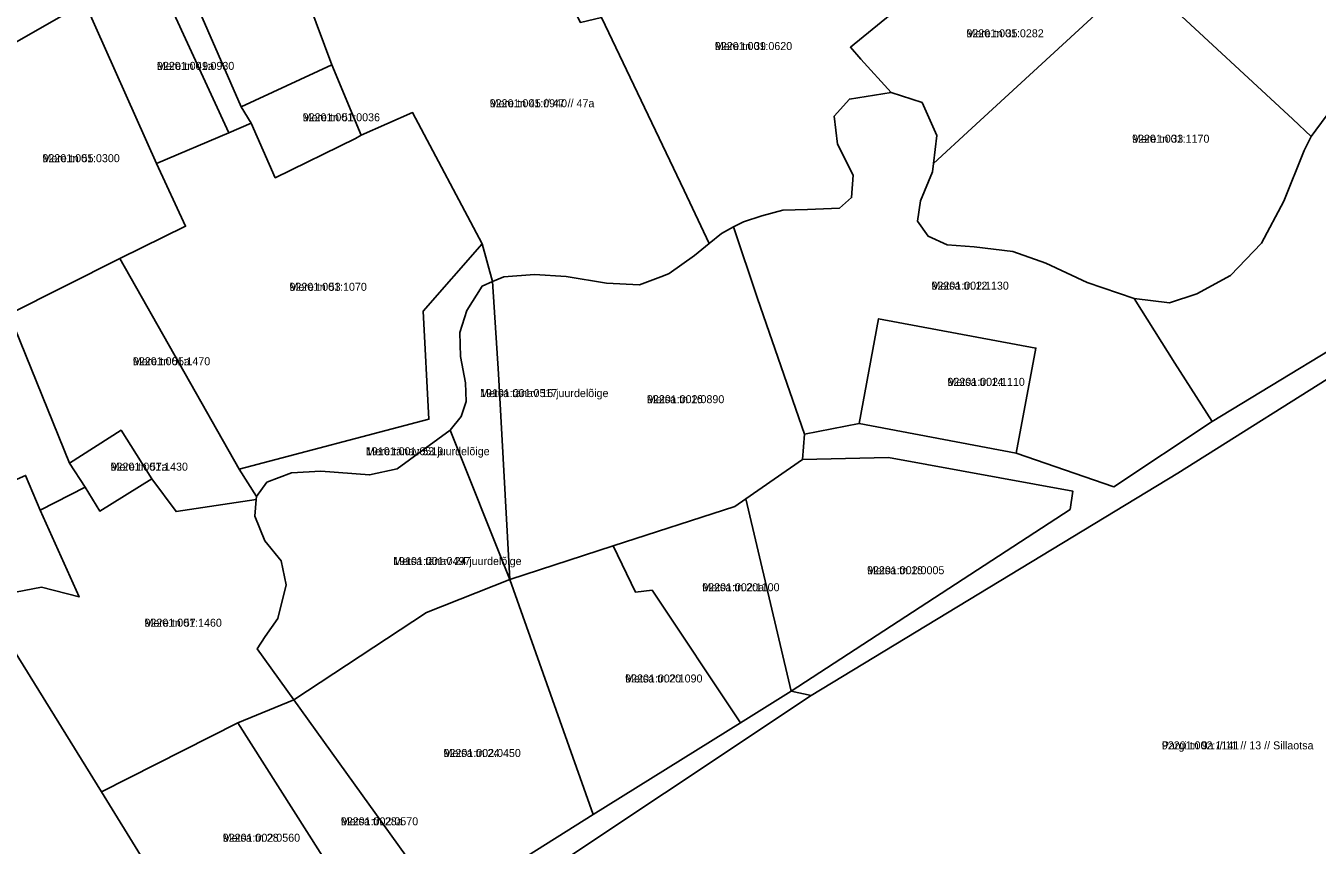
# Model space of a CAD drawing. Extents: x 601493 to 643081, y 6584980 to 6634019.
# Drawn here: x 610866.3 to 611108.4, y 6605821.9 to 6605975.5 of the extents above; entities that cross this region are included whole.
import ezdxf

# ---------------------------------------------------------------- set-up
doc = ezdxf.new("R2010")
doc.units = 0
for name, color, linetype in [('L_AADRESS', 7, 'Continuous'), ('PIIR', 7, 'Continuous'), ('TUNNUS', 7, 'Continuous')]:
    doc.layers.add(name, color=color, linetype=linetype)

msp = doc.modelspace()

# ---------------------------------------------------------------- linework, layer by layer
at = {"layer": 'PIIR'}
for points in [[(611128.64, 6606165.01), (611097.49, 6606138.32), (611089.51, 6606133.5), (611038.62, 6606094.13), (611015.12, 6606075.83), (610999.16, 6606063.8), (610995.18, 6606060.82), (610969.72, 6606041.76), (610962.39, 6606036.06), (610945.03, 6606023.2), (610934.02, 6606015.29), (610912.09, 6605999.25), (610894.18, 6605989.02), (610906.68, 6605960.32), (610908.5, 6605957.28), (610904.36, 6605955.48), (610889.96, 6605986.73), (610877.35, 6605979.85), (610842.57, 6605960.03)], [(611028.31, 6605977.57), (611020.89, 6605971.5), (611022.85, 6605969.3), (611028.54, 6605963.01), (611020.7, 6605961.78), (611017.81, 6605958.58), (611018.43, 6605953.33), (611021.42, 6605947.55), (611021.1, 6605943.32), (611018.83, 6605941.37), (611012.85, 6605941.11), (611008.22, 6605940.98), (611004.3, 6605939.92), (611000.81, 6605938.8), (610998.97, 6605937.83), (610996.69, 6605936.59), (610994.4, 6605934.72), (610989.72, 6605944.68), (610974.24, 6605977.06)], [(610863.17, 6605921.48), (610874.48, 6605893.56), (610877.42, 6605889.07), (610868.99, 6605884.72), (610866.22, 6605891.26)], [(610944.64, 6605810.06), (610972.65, 6605827.71), (611000.25, 6605844.9), (611009.76, 6605850.83), (611013.55, 6605849.98), (610931.04, 6605795.1)]]:
    msp.add_lwpolyline(points, dxfattribs=at)
for points in [[(611039.61, 6606017.31), (611054.32, 6606028.38), (611056.76, 6606025.9), (611072.83, 6606007.94), (611094.39, 6605989.62), (611096.54, 6605991.79), (611117.79, 6605970.79), (611120.89, 6605967.72), (611118.94, 6605965.75), (611110.9, 6605959.65), (611110.08, 6605958.56), (611107.28, 6605954.8), (611103.8, 6605958.04), (611079.61, 6605980.43), (611073.09, 6605983.62)], [(610912.09, 6605999.25), (610934.02, 6606015.29), (610947.98, 6605988.25), (610960.68, 6605994.97), (610970.25, 6605976.15), (610974.24, 6605977.06), (610989.72, 6605944.68), (610994.4, 6605934.72), (610991.63, 6605932.47), (610986.89, 6605929.07), (610985.82, 6605928.67), (610981.32, 6605927), (610975.14, 6605927.31), (610967.61, 6605928.55), (610961.67, 6605928.89), (610955.93, 6605928.5), (610953.77, 6605927.57), (610951.82, 6605934.68), (610938.78, 6605959.26), (610929.15, 6605955.05), (610923.67, 6605968.23)], [(610923.67, 6605968.23), (610906.68, 6605960.32), (610894.18, 6605989.02), (610912.09, 6605999.25)], [(611043.62, 6605956.34), (611036.45, 6605949.71), (611037.09, 6605954.97), (611034.31, 6605961.16), (611028.54, 6605963.01), (611022.85, 6605969.3), (611020.89, 6605971.5), (611028.31, 6605977.57), (611052.1, 6605997.02), (611069.86, 6605980.54)], [(610877.35, 6605979.85), (610889.96, 6605986.73), (610904.36, 6605955.48), (610890.78, 6605949.7)], [(611009.76, 6605850.83), (611062.06, 6605884.88), (611062.56, 6605888.3), (611027.99, 6605894.63), (611011.92, 6605894.26), (611012.29, 6605899.01), (611022.49, 6605900.98), (611051.97, 6605895.45), (611070.25, 6605889.12), (611088.7, 6605901.38), (611123.51, 6605922.45), (611134.49, 6605927.03), (611165.05, 6605954.92), (611179.05, 6605967.82), (611186.58, 6605975.54), (611199.99, 6605983.63), (611201.01, 6605979.17), (611192.29, 6605975.95), (611158.84, 6605942.95), (611147.96, 6605926.34), (611137.5, 6605923.67), (611115.81, 6605912.81), (611082.29, 6605891.66), (611013.55, 6605849.98)], [(611036.26, 6605948.17), (611036.45, 6605949.71), (611043.62, 6605956.34), (611069.86, 6605980.54), (611073.09, 6605983.62), (611079.61, 6605980.43), (611103.8, 6605958.04), (611107.28, 6605954.8), (611107.25, 6605954.76), (611105.98, 6605952.13), (611102.16, 6605942.64), (611097.93, 6605934.81), (611092.15, 6605928.73), (611085.81, 6605925.29), (611080.7, 6605923.59), (611074.1, 6605924.42), (611065.24, 6605927.41), (611057.51, 6605931.02), (611051.32, 6605933.19), (611044.1, 6605934.12), (611039.04, 6605934.45), (611035.43, 6605936.1), (611033.47, 6605938.89), (611033.99, 6605942.7)], [(610877.35, 6605979.85), (610890.78, 6605949.7), (610896.22, 6605937.94), (610883.9, 6605931.88), (610863.17, 6605921.48), (610842.57, 6605960.03)], [(610906.68, 6605960.32), (610923.67, 6605968.23), (610929.15, 6605955.05), (610928.06, 6605954.4), (610913.03, 6605947.04), (610908.5, 6605957.28)], [(611065.24, 6605927.41), (611074.1, 6605924.42), (611081.69, 6605912.32), (611088.7, 6605901.38), (611070.25, 6605889.12), (611051.97, 6605895.45), (611055.65, 6605915.11), (611026.17, 6605920.63), (611022.49, 6605900.98), (611012.29, 6605899.01), (611003.46, 6605924.41), (610998.97, 6605937.83), (611000.81, 6605938.8), (611004.3, 6605939.92), (611008.22, 6605940.98), (611012.85, 6605941.11), (611018.83, 6605941.37), (611021.1, 6605943.32), (611021.42, 6605947.55), (611018.43, 6605953.33), (611017.81, 6605958.58), (611020.7, 6605961.78), (611028.54, 6605963.01), (611034.31, 6605961.16), (611037.09, 6605954.97), (611036.45, 6605949.71), (611036.26, 6605948.17), (611033.99, 6605942.7), (611033.47, 6605938.89), (611035.43, 6605936.1), (611039.04, 6605934.45), (611044.1, 6605934.12), (611051.32, 6605933.19), (611057.51, 6605931.02)], [(610904.36, 6605955.48), (610908.5, 6605957.28), (610913.03, 6605947.04), (610928.06, 6605954.4), (610929.15, 6605955.05), (610938.78, 6605959.26), (610951.82, 6605934.68), (610940.76, 6605922.04), (610941.85, 6605901.79), (610906.3, 6605892.43), (610883.9, 6605931.88), (610896.22, 6605937.94), (610890.78, 6605949.7)], [(611110.08, 6605958.56), (611117.01, 6605949.26), (611120.11, 6605944.23), (611134.49, 6605927.03), (611123.51, 6605922.45), (611088.7, 6605901.38), (611081.69, 6605912.32), (611074.1, 6605924.42), (611080.7, 6605923.59), (611085.81, 6605925.29), (611092.15, 6605928.73), (611097.93, 6605934.81), (611102.16, 6605942.64), (611105.98, 6605952.13), (611107.25, 6605954.76), (611107.28, 6605954.8)], [(610998.97, 6605937.83), (611003.46, 6605924.41), (611012.29, 6605899.01), (611011.92, 6605894.26), (611001.24, 6605886.83), (610999.22, 6605885.43), (610976.42, 6605878.04), (610957.04, 6605871.76), (610954.88, 6605910.29), (610953.77, 6605927.57), (610955.93, 6605928.5), (610961.67, 6605928.89), (610967.61, 6605928.55), (610975.14, 6605927.31), (610981.32, 6605927), (610985.82, 6605928.67), (610986.89, 6605929.07), (610991.63, 6605932.47), (610994.4, 6605934.72), (610996.69, 6605936.59)], [(610906.3, 6605892.43), (610941.85, 6605901.79), (610940.76, 6605922.04), (610951.82, 6605934.68), (610953.77, 6605927.57), (610951.81, 6605926.73), (610948.98, 6605922.15), (610947.64, 6605918.06), (610947.79, 6605913.53), (610948.71, 6605908.58), (610948.82, 6605905.08), (610947.89, 6605902.29), (610945.82, 6605899.72), (610935.9, 6605892.47), (610930.74, 6605891.33), (610921.58, 6605892.06), (610916.12, 6605891.75), (610911.48, 6605890), (610909.52, 6605887.32)], [(610863.17, 6605921.48), (610883.9, 6605931.88), (610906.3, 6605892.43), (610909.52, 6605887.32), (610909.47, 6605886.73), (610894.45, 6605884.46), (610889.9, 6605890.6), (610884.14, 6605899.73), (610874.48, 6605893.56)], [(611039.07, 6605812.36), (611001.4, 6605788.06), (610929.47, 6605759.72), (610910.09, 6605783.32), (610921.07, 6605788.83), (610931.04, 6605795.1), (611013.55, 6605849.98), (611082.29, 6605891.66), (611115.81, 6605912.81), (611137.5, 6605923.67), (611147.96, 6605926.34), (611157.22, 6605925.86), (611165.66, 6605923.69), (611197.19, 6605914.12), (611207.12, 6605912.54), (611210.66, 6605912.84), (611218.77, 6605915.13), (611225.45, 6605916.03), (611183.62, 6605885.37), (611170.92, 6605860.77), (611135.45, 6605791.96), (611115.08, 6605753.45), (611094.98, 6605768.18), (611075.19, 6605763.83)], [(610957.04, 6605871.76), (610945.82, 6605899.72), (610947.89, 6605902.29), (610948.82, 6605905.08), (610948.71, 6605908.58), (610947.79, 6605913.53), (610947.64, 6605918.06), (610948.98, 6605922.15), (610951.81, 6605926.73), (610953.77, 6605927.57), (610954.88, 6605910.29)], [(611026.17, 6605920.63), (611055.65, 6605915.11), (611051.97, 6605895.45), (611022.49, 6605900.98)], [(610877.42, 6605889.07), (610874.48, 6605893.56), (610884.14, 6605899.73), (610889.9, 6605890.6), (610880.15, 6605884.55)], [(610941.42, 6605865.54), (610916.52, 6605849.17), (610909.66, 6605858.72), (610911.15, 6605861.03), (610913.53, 6605864.43), (610915.08, 6605870.72), (610914.15, 6605875.25), (610911.06, 6605878.97), (610909.21, 6605883.61), (610909.47, 6605886.73), (610909.52, 6605887.32), (610911.48, 6605890), (610916.12, 6605891.75), (610921.58, 6605892.06), (610930.74, 6605891.33), (610935.9, 6605892.47), (610945.82, 6605899.72), (610957.04, 6605871.76)], [(611011.92, 6605894.26), (611027.99, 6605894.63), (611062.56, 6605888.3), (611062.06, 6605884.88), (611009.76, 6605850.83), (611001.24, 6605886.83)], [(610846.82, 6605852.96), (610841.61, 6605851.14), (610838.14, 6605850.04), (610833.29, 6605846.64), (610829.65, 6605842.78), (610828.44, 6605841.49), (610823.18, 6605833.34), (610818.43, 6605824.64), (610811.54, 6605839.81), (610800.48, 6605864.16), (610827.09, 6605876.12), (610827.85, 6605874.34), (610866.22, 6605891.26), (610868.99, 6605884.72), (610876.27, 6605868.49), (610869.21, 6605870.28), (610864.36, 6605869.35), (610861.47, 6605867.5), (610860.54, 6605864.2), (610860.33, 6605858.94), (610858.17, 6605855.64), (610853.73, 6605853.27), (610850.54, 6605853.06)], [(610869.21, 6605870.28), (610876.27, 6605868.49), (610868.99, 6605884.72), (610877.42, 6605889.07), (610880.15, 6605884.55), (610889.9, 6605890.6), (610894.45, 6605884.46), (610909.47, 6605886.73), (610909.21, 6605883.61), (610911.06, 6605878.97), (610914.15, 6605875.25), (610915.08, 6605870.72), (610913.53, 6605864.43), (610911.15, 6605861.03), (610909.66, 6605858.72), (610916.52, 6605849.17), (610906.04, 6605844.85), (610880.44, 6605831.95), (610862.06, 6605861.72), (610860.54, 6605864.2), (610861.47, 6605867.5), (610864.36, 6605869.35)], [(610980.61, 6605869.36), (610976.42, 6605878.04), (610999.22, 6605885.43), (611001.24, 6605886.83), (611009.76, 6605850.83), (611000.25, 6605844.9), (610983.7, 6605869.74)], [(610957.04, 6605871.76), (610976.42, 6605878.04), (610980.61, 6605869.36), (610983.7, 6605869.74), (611000.25, 6605844.9), (610972.65, 6605827.71)], [(610941.42, 6605865.54), (610957.04, 6605871.76), (610972.65, 6605827.71), (610944.64, 6605810.06), (610916.52, 6605849.17)], [(610852.47, 6605809.13), (610847.26, 6605816.83), (610834.07, 6605836.28), (610829.65, 6605842.78), (610833.29, 6605846.64), (610838.14, 6605850.04), (610841.61, 6605851.14), (610846.82, 6605852.96), (610850.54, 6605853.06), (610853.73, 6605853.27), (610858.17, 6605855.64), (610860.33, 6605858.94), (610860.54, 6605864.2), (610862.06, 6605861.72), (610880.44, 6605831.95), (610896.61, 6605805.75), (610908.41, 6605787.66), (610877.74, 6605778.64), (610856.61, 6605804.18)], [(610906.04, 6605844.85), (610916.52, 6605849.17), (610944.64, 6605810.06), (610932.85, 6605802.49), (610921.49, 6605820.55)], [(610880.44, 6605831.95), (610906.04, 6605844.85), (610921.49, 6605820.55), (610932.85, 6605802.49), (610929.31, 6605800.33), (610917.86, 6605818.92), (610896.61, 6605805.75)]]:
    msp.add_lwpolyline(points, close=True, dxfattribs=at)

# ---------------------------------------------------------------- texts
at = {"layer": 'L_AADRESS'}
for s, p in [('Mere tn 35', (611042.62, 6605973.37)), ('Mere tn 39', (610995.46, 6605970.98)), ('Mere tn 49a', (610890.86, 6605967.26)), ('Mere tn 45 // 47 // 47a', (610953.25, 6605960.26)), ('Mere tn 51', (610918.18, 6605957.63)), ('Mere tn 33', (611073.68, 6605953.61)), ('Mere tn 55', (610869.39, 6605949.96)), ('Metsa tn 12', (611036.07, 6605926.07)), ('Mere tn 53', (610915.71, 6605925.85)), ('Mere tn 55a', (610886.35, 6605911.9)), ('Metsa tn 14', (611039.07, 6605908.04)), ('Metsa tänav 16 juurdelõige', (610951.43, 6605905.93)), ('Metsa tn 16', (610982.73, 6605904.79)), ('Mere tänav 53 juurdelõige', (610930.04, 6605895.03)), ('Mere tn 57a', (610882.17, 6605892.14)), ('Metsa tänav 24 juurdelõige', (610935.14, 6605874.45)), ('Metsa tn 18', (611023.99, 6605872.73)), ('Metsa tn 20a', (610993.09, 6605869.54)), ('Mere tn 57', (610888.53, 6605862.89)), ('Metsa tn 20', (610978.64, 6605852.44)), ('Pargi tn 9a // 11 // 13 // Sillaotsa', (611079.27, 6605839.9)), ('Metsa tn 24', (610944.59, 6605838.47)), ('Metsa tn 28a', (610925.34, 6605825.67)), ('Metsa tn 28', (610903.2, 6605822.59))]:
    msp.add_text(s, height=1.5, dxfattribs=at).set_placement(p)
at = {"layer": 'TUNNUS'}
for s, p in [('92201:001:0282', (611042.62, 6605973.37)), ('92201:001:0620', (610995.46, 6605970.98)), ('92201:001:0930', (610890.86, 6605967.26)), ('92201:001:0940', (610953.25, 6605960.26)), ('92201:001:0036', (610918.18, 6605957.63)), ('92201:001:1170', (611073.68, 6605953.61)), ('92201:001:0300', (610869.39, 6605949.96)), ('92201:002:1130', (611036.07, 6605926.07)), ('92201:001:1070', (610915.71, 6605925.85)), ('92201:001:1470', (610886.35, 6605911.9)), ('92201:002:1110', (611039.07, 6605908.04)), ('19101:001:0517', (610951.43, 6605905.93)), ('92201:002:0890', (610982.73, 6605904.79)), ('19101:001:0519', (610930.04, 6605895.03)), ('92201:001:1430', (610882.17, 6605892.14)), ('19101:001:0497', (610935.14, 6605874.45)), ('92201:002:0005', (611023.99, 6605872.73)), ('92201:002:1100', (610993.09, 6605869.54)), ('92201:001:1460', (610888.53, 6605862.89)), ('92201:002:1090', (610978.64, 6605852.44)), ('92201:002:1141', (611079.27, 6605839.9)), ('92201:002:0450', (610944.59, 6605838.47)), ('92201:002:0570', (610925.34, 6605825.67)), ('92201:002:0560', (610903.2, 6605822.59))]:
    msp.add_text(s, height=1.5, dxfattribs=at).set_placement(p)

doc.saveas('drawing.dxf')
